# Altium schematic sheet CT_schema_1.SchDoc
size 386 x 337 mm
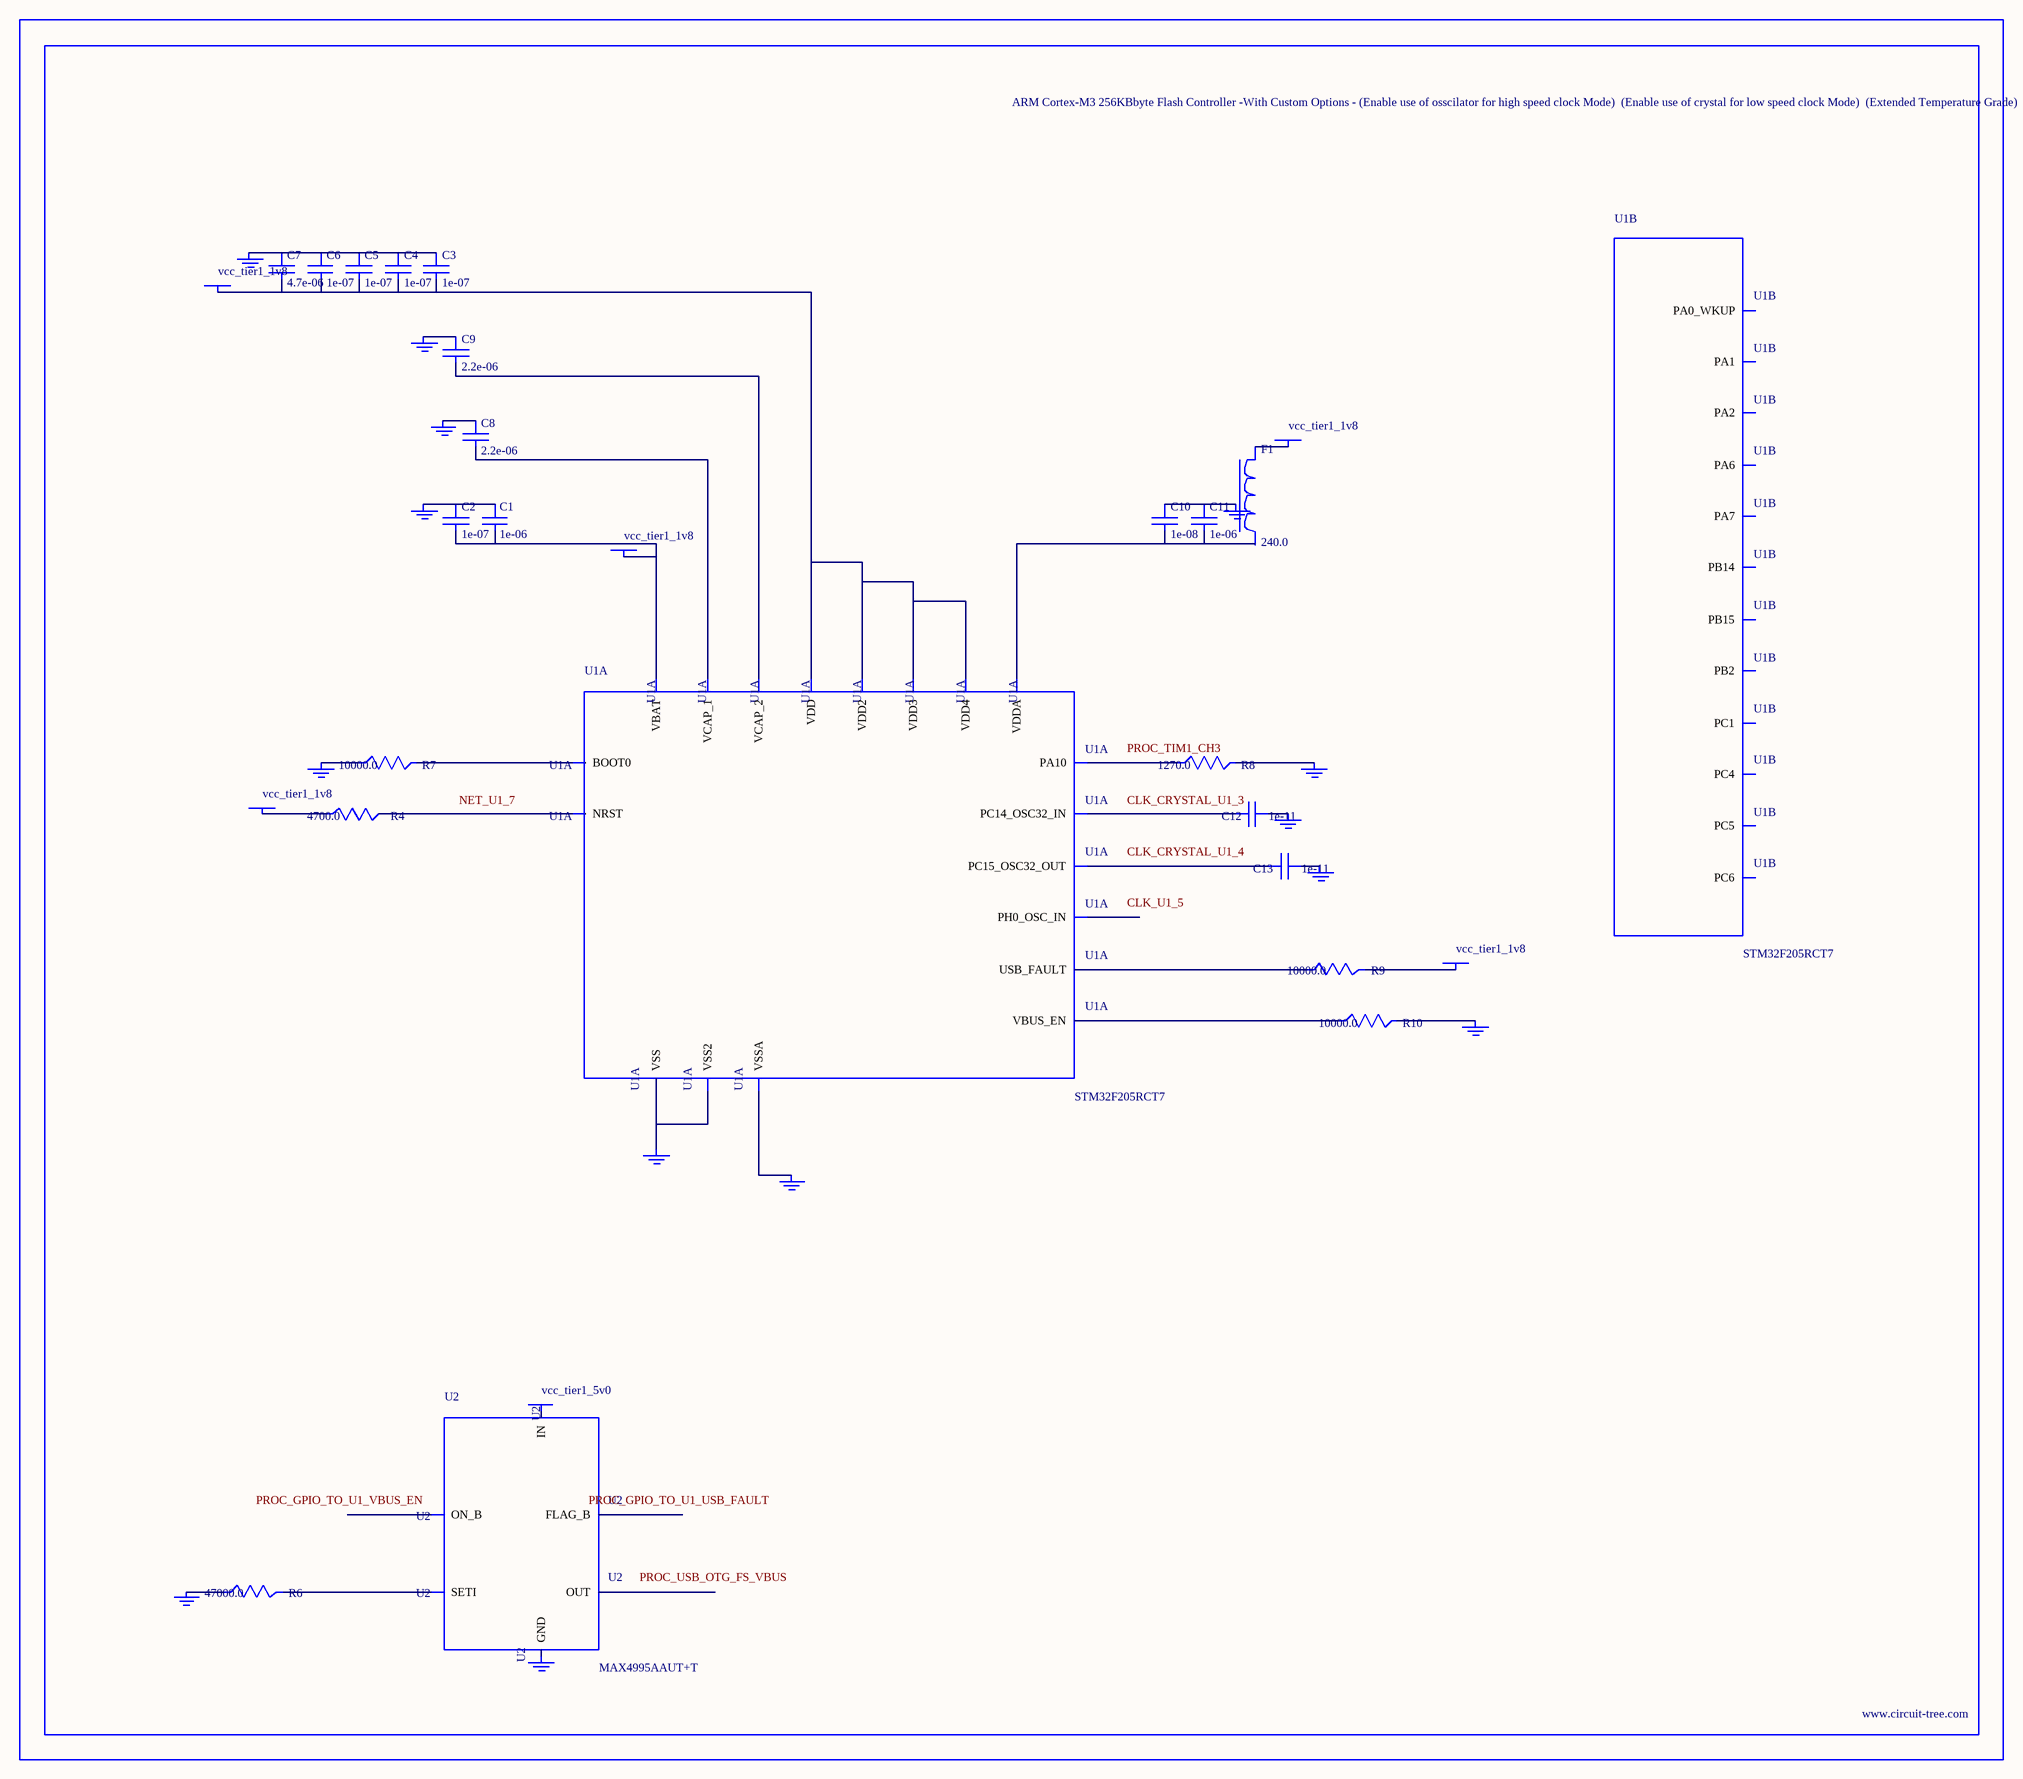
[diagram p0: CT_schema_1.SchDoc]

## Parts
BORDER0  (no value)
C1  1e-06  [C0603]
C2  1e-07  [C0603]
C3  1e-07  [C0603]
C4  1e-07  [C0603]
C5  1e-07  [C0603]
C6  1e-07  [C0603]
C7  4.7e-06  [C0603]
C8  2.2e-06  [C0603]
C9  2.2e-06  [C0603]
C10  1e-08  [C0603]
C11  1e-06  [C0603]
C12  1e-11  [C0402]
C13  1e-11  [C0402]
F1  240.0  [L0603]
GND_INSTANCE_0_0  (no value)
GND_INSTANCE_0_1  (no value)
GND_INSTANCE_0_2  (no value)
GND_INSTANCE_0_3  (no value)
GND_INSTANCE_0_4  (no value)
GND_INSTANCE_0_5  (no value)
GND_INSTANCE_0_6  (no value)
GND_INSTANCE_0_7  (no value)
GND_INSTANCE_0_8  (no value)
GND_INSTANCE_0_9  (no value)
GND_INSTANCE_0_10  (no value)
GND_INSTANCE_0_11  (no value)
GND_INSTANCE_0_12  (no value)
GND_INSTANCE_0_13  (no value)
POWER_INSTANCE_0_0  vcc_tier1_1v8
POWER_INSTANCE_0_1  vcc_tier1_1v8
POWER_INSTANCE_0_2  vcc_tier1_1v8
POWER_INSTANCE_0_3  vcc_tier1_1v8
POWER_INSTANCE_0_4  vcc_tier1_1v8
POWER_INSTANCE_0_5  vcc_tier1_5v0
R4  4700.0  [R0603]
R6  47000.0  [R0603]
R7  10000.0  [R0603]
R8  1270.0  [R0603]
R9  10000.0  [R0603]
R10  10000.0  [R0603]
U1  STM32F205RCT7  [LQFP64]  (parts A,B of 7)
U2  MAX4995AAUT+T  [SOT-23-6]

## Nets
NetC1_1: C1.1 C2.1 GND_INSTANCE_0_0.0(GND)
NetC1_2: C1.2 C2.2 POWER_INSTANCE_0_0.0(PWR) U1.1(VBAT)
NetC3_1: C3.1 C4.1 C5.1 C6.1 C7.1 GND_INSTANCE_0_6.0(GND)
NetC3_2: C3.2 C4.2 C5.2 C6.2 C7.2 POWER_INSTANCE_0_3.0(PWR) U1.19(VDD) U1.32(VDD2) U1.48(VDD3) U1.64(VDD4)
NetC8_1: C8.1 GND_INSTANCE_0_7.0(GND)
NetC8_2: C8.2 U1.31(VCAP_1)
NetC9_1: C9.1 GND_INSTANCE_0_9.0(GND)
NetC9_2: C9.2 U1.47(VCAP_2)
NetC10_1: C10.1 C11.1 GND_INSTANCE_0_5.0(GND)
NetC10_2: C10.2 C11.2 U1.13(VDDA)
NetC12_1: C12.1 GND_INSTANCE_0_2.0(GND)
NetC12_2: C12.2 U1.3(PC14_OSC32_IN)
NetC13_1: C13.1 GND_INSTANCE_0_3.0(GND)
NetC13_2: C13.2 U1.4(PC15_OSC32_OUT)
NetF1_1: F1.1 POWER_INSTANCE_0_2.0(PWR)
NetGND_INSTANCE_0_1_0: GND_INSTANCE_0_1.0(GND) R10.2
NetGND_INSTANCE_0_4_0: GND_INSTANCE_0_4.0(GND) U1.12(VSSA)
NetGND_INSTANCE_0_8_0: GND_INSTANCE_0_8.0(GND) R8.2
NetGND_INSTANCE_0_10_0: GND_INSTANCE_0_10.0(GND) R7.1
NetGND_INSTANCE_0_11_0: GND_INSTANCE_0_11.0(GND) U1.18(VSS) U1.63(VSS2)
NetGND_INSTANCE_0_12_0: GND_INSTANCE_0_12.0(GND) R6.1
NetPOWER_INSTANCE_0_1_0: POWER_INSTANCE_0_1.0(PWR) R9.2
NetPOWER_INSTANCE_0_4_0: POWER_INSTANCE_0_4.0(PWR) R4.1
NetR4_2: R4.2 U1.7(NRST)
NetR6_2: R6.2 U2.3(SETI)
NetR7_2: R7.2 U1.60(BOOT0)
NetR8_1: R8.1 U1.43(PA10)
NetR9_1: R9.1 U1.6(USB_FAULT)
NetR10_1: R10.1 U1.2(VBUS_EN)

Not connected (* = marked no-connect by the designer): F1 2; GND_INSTANCE_0_13 0(GND); POWER_INSTANCE_0_5 0(PWR); U1 5(PH0_OSC_IN) 9(PC1) 14(PA0_WKUP) 15(PA1) 16(PA2) 22(PA6) 23(PA7) 24(PC4) 25(PC5) 28(PB2) 35(PB14) 36(PB15) 37(PC6); U2 1(OUT) 2(GND) 4(ON_B) 5(IN) 6(FLAG_B)

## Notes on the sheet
- Labels drawn without touching a wire or pin: CLK_CRYSTAL_U1_3, CLK_CRYSTAL_U1_4, CLK_U1_5, NET_U1_7, PROC_GPIO_TO_U1_USB_FAULT, PROC_GPIO_TO_U1_VBUS_EN, PROC_TIM1_CH3, PROC_USB_OTG_FS_VBUS

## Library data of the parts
BORDER0 = BORDER_PAGE0
C1 C11 = C0603C105K3RACTU
C2-C6 = 06035C104K4Z2A
C7 = GRM188R6YA475KE15D
C8 C9 = C0603C225K8RACTU
C10 = 06035C103K4Z2A
C12 C13 = C0402C100K3GACTU
F1 = Z0603C241ASMST
GND_INSTANCE_0_0-GND_INSTANCE_0_13 = GND
POWER_INSTANCE_0_0-POWER_INSTANCE_0_5 = PWR
R4 = RC0603JR-074K7L
R6 = RC0603JR-0747KL
R7 R9 R10 = RC0603JR-0710KL
R8 = RC0603FR-071K27L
